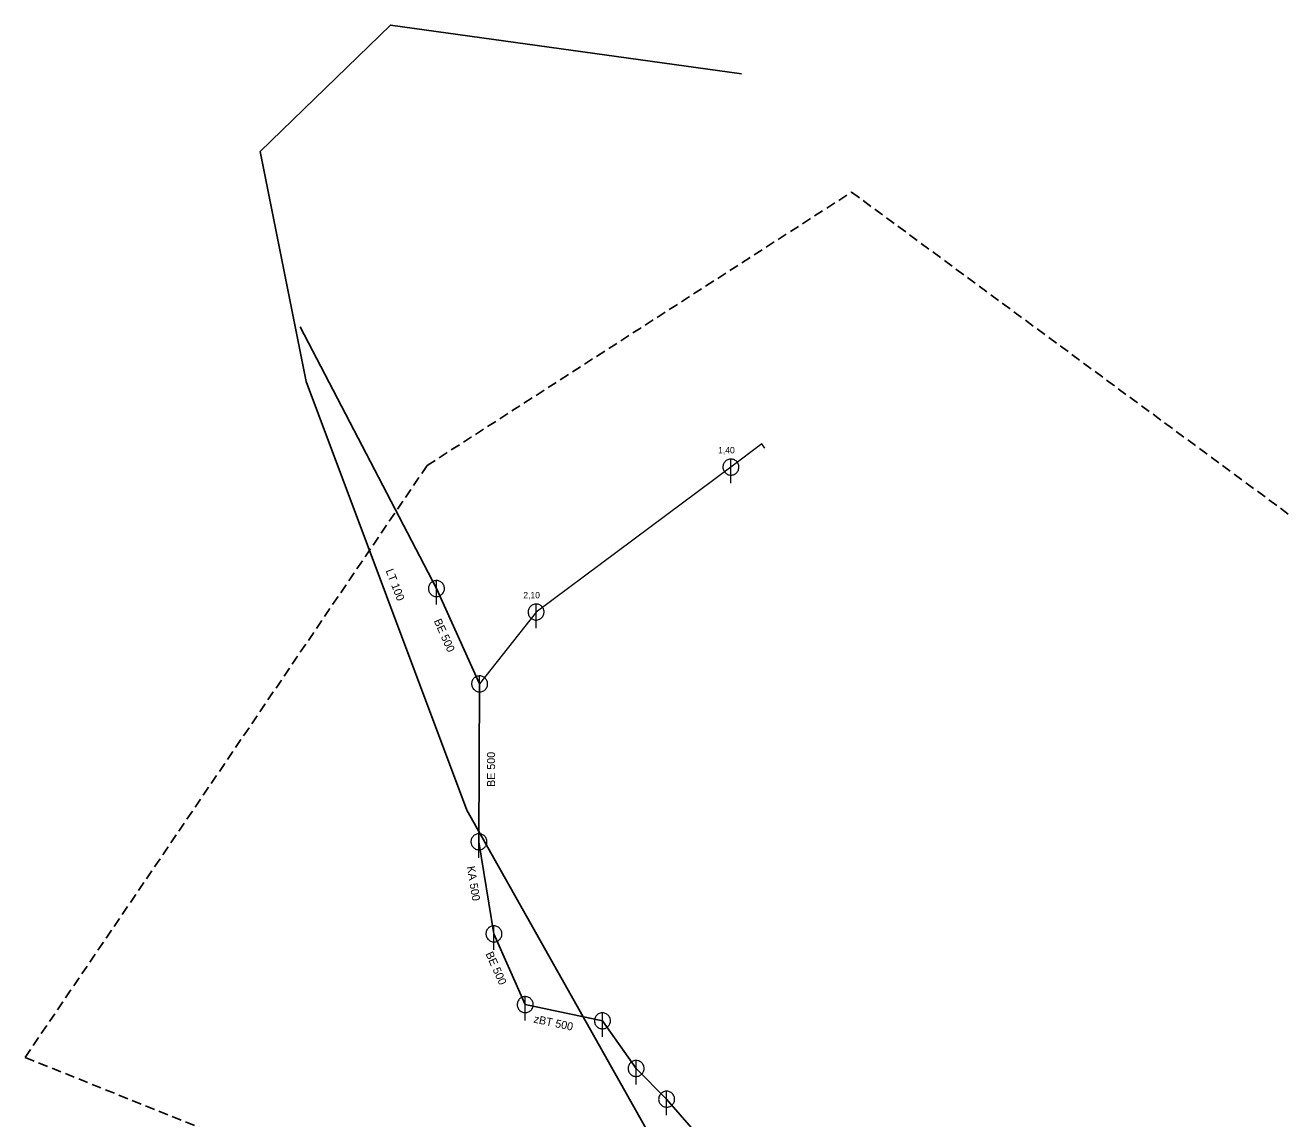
# Model space of a CAD drawing. Extents: x -687195 to -686201, y -974149 to -973877.
# Drawn here: x -687195.2 to -687038.1, y -974013.8 to -973877.2 of the extents above; entities that cross this region are included whole.
import ezdxf

# ---------------------------------------------------------------- set-up
doc = ezdxf.new("R2010")
doc.units = 0
doc.header["$LTSCALE"] = 0.4
doc.linetypes.add('MEDIUM_DASHED', pattern=[4.5, 3, -1.5])
doc.layers.add('1', color=7, linetype='Continuous')
for name, color, linetype, lineweight in [('11', 7, 'Continuous', 13), ('14', 7, 'Continuous', 25), ('17', 7, 'Continuous', 25), ('22', 7, 'Continuous', 13), ('63', 7, 'MEDIUM_DASHED', 25)]:
    doc.layers.add(name, color=color, linetype=linetype, lineweight=lineweight)

msp = doc.modelspace()

# ---------------------------------------------------------------- linework, layer by layer
at = {"layer": '11'}
for p, q in [((-687106.99, -973932.4), (-687131.34, -973950.51)), ((-687131.34, -973950.51), (-687138.399, -973959.489))]:
    msp.add_line(p, q, dxfattribs=at)
msp.add_lwpolyline([(-687102.74, -973930.05), (-687103.13, -973929.48), (-687106.99, -973932.4)], dxfattribs=at)
at = {"layer": '14'}
for p, q in [((-687160.836, -973914.878), (-687143.793, -973947.573)), ((-687143.793, -973947.573), (-687138.399, -973959.489)), ((-687138.399, -973959.489), (-687138.481, -973979.218)), ((-687138.481, -973979.218), (-687136.605, -973990.725)), ((-687136.605, -973990.725), (-687132.697, -973999.562)), ((-687132.697, -973999.562), (-687123.045, -974001.587)), ((-687123.045, -974001.587), (-687118.837, -974007.541)), ((-687118.837, -974007.541), (-687115.021, -974011.379)), ((-687115.021, -974011.379), (-687111.634, -974015.295))]:
    msp.add_line(p, q, dxfattribs=at)
at = {"layer": '17'}
msp.add_lwpolyline([(-687124.395, -974028.598), (-687113.714, -974021.973), (-687139.989, -973975.271), (-687160.068, -973921.704), (-687165.829, -973892.978), (-687149.548, -973877.175), (-687105.661, -973883.258)], dxfattribs=at)
at = {"layer": '22'}
for p, q in [((-687106.99, -973934.4), (-687106.989, -973931.4)), ((-687143.793, -973949.573), (-687143.792, -973946.573)), ((-687131.34, -973952.51), (-687131.339, -973949.51)), ((-687138.399, -973961.489), (-687138.398, -973958.489)), ((-687138.481, -973981.218), (-687138.48, -973978.218)), ((-687136.605, -973992.725), (-687136.604, -973989.725)), ((-687132.697, -974001.562), (-687132.696, -973998.562)), ((-687123.045, -974003.587), (-687123.044, -974000.587)), ((-687118.837, -974009.541), (-687118.836, -974006.541)), ((-687115.021, -974013.379), (-687115.02, -974010.379))]:
    msp.add_line(p, q, dxfattribs=at)
for points in [[(-687105.99, -973932.4), (-687105.995, -973932.291), (-687106.013, -973932.183), (-687106.043, -973932.077), (-687106.083, -973931.976), (-687106.135, -973931.879), (-687106.197, -973931.789), (-687106.269, -973931.706), (-687106.349, -973931.632), (-687106.437, -973931.566), (-687106.531, -973931.511), (-687106.631, -973931.466), (-687106.736, -973931.433), (-687106.843, -973931.411), (-687106.952, -973931.401), (-687107.062, -973931.403), (-687107.17, -973931.417), (-687107.277, -973931.442), (-687107.38, -973931.479), (-687107.478, -973931.528), (-687107.57, -973931.586), (-687107.656, -973931.655), (-687107.733, -973931.732), (-687107.802, -973931.818), (-687107.861, -973931.91), (-687107.909, -973932.008), (-687107.946, -973932.111), (-687107.972, -973932.218), (-687107.986, -973932.326), (-687107.989, -973932.436), (-687107.979, -973932.545), (-687107.958, -973932.652), (-687107.924, -973932.756), (-687107.88, -973932.856), (-687107.825, -973932.951), (-687107.759, -973933.039), (-687107.685, -973933.119), (-687107.602, -973933.191), (-687107.512, -973933.253), (-687107.416, -973933.305), (-687107.314, -973933.346), (-687107.209, -973933.376), (-687107.101, -973933.394), (-687106.991, -973933.4), (-687106.882, -973933.394), (-687106.774, -973933.376), (-687106.669, -973933.347), (-687106.567, -973933.306), (-687106.47, -973933.254), (-687106.38, -973933.192), (-687106.297, -973933.121), (-687106.222, -973933.041), (-687106.157, -973932.953), (-687106.101, -973932.859), (-687106.057, -973932.759), (-687106.023, -973932.655), (-687106.001, -973932.547), (-687105.991, -973932.438)], [(-687142.793, -973947.573), (-687142.798, -973947.464), (-687142.816, -973947.356), (-687142.846, -973947.25), (-687142.886, -973947.149), (-687142.938, -973947.052), (-687143, -973946.962), (-687143.072, -973946.879), (-687143.152, -973946.805), (-687143.24, -973946.739), (-687143.334, -973946.684), (-687143.434, -973946.639), (-687143.539, -973946.606), (-687143.646, -973946.584), (-687143.755, -973946.574), (-687143.865, -973946.576), (-687143.973, -973946.59), (-687144.08, -973946.615), (-687144.183, -973946.652), (-687144.281, -973946.701), (-687144.373, -973946.759), (-687144.459, -973946.828), (-687144.536, -973946.905), (-687144.605, -973946.991), (-687144.664, -973947.083), (-687144.712, -973947.181), (-687144.749, -973947.284), (-687144.775, -973947.391), (-687144.789, -973947.499), (-687144.792, -973947.609), (-687144.782, -973947.718), (-687144.761, -973947.825), (-687144.727, -973947.929), (-687144.683, -973948.029), (-687144.628, -973948.124), (-687144.562, -973948.212), (-687144.488, -973948.292), (-687144.405, -973948.364), (-687144.315, -973948.426), (-687144.219, -973948.478), (-687144.117, -973948.519), (-687144.012, -973948.549), (-687143.904, -973948.567), (-687143.794, -973948.573), (-687143.685, -973948.567), (-687143.577, -973948.549), (-687143.472, -973948.52), (-687143.37, -973948.479), (-687143.273, -973948.427), (-687143.183, -973948.365), (-687143.1, -973948.294), (-687143.025, -973948.214), (-687142.96, -973948.126), (-687142.904, -973948.032), (-687142.86, -973947.932), (-687142.826, -973947.828), (-687142.804, -973947.72), (-687142.794, -973947.611)], [(-687130.34, -973950.51), (-687130.345, -973950.401), (-687130.363, -973950.293), (-687130.393, -973950.187), (-687130.433, -973950.086), (-687130.485, -973949.989), (-687130.547, -973949.899), (-687130.619, -973949.816), (-687130.699, -973949.742), (-687130.787, -973949.676), (-687130.881, -973949.621), (-687130.981, -973949.576), (-687131.086, -973949.543), (-687131.193, -973949.521), (-687131.302, -973949.511), (-687131.412, -973949.513), (-687131.52, -973949.527), (-687131.627, -973949.552), (-687131.73, -973949.589), (-687131.828, -973949.638), (-687131.92, -973949.696), (-687132.006, -973949.765), (-687132.083, -973949.842), (-687132.152, -973949.928), (-687132.211, -973950.02), (-687132.259, -973950.118), (-687132.296, -973950.221), (-687132.322, -973950.328), (-687132.336, -973950.436), (-687132.339, -973950.546), (-687132.329, -973950.655), (-687132.308, -973950.762), (-687132.274, -973950.866), (-687132.23, -973950.966), (-687132.175, -973951.061), (-687132.109, -973951.149), (-687132.035, -973951.229), (-687131.952, -973951.301), (-687131.862, -973951.363), (-687131.766, -973951.415), (-687131.664, -973951.456), (-687131.559, -973951.486), (-687131.451, -973951.504), (-687131.341, -973951.51), (-687131.232, -973951.504), (-687131.124, -973951.486), (-687131.019, -973951.457), (-687130.917, -973951.416), (-687130.82, -973951.364), (-687130.73, -973951.302), (-687130.647, -973951.231), (-687130.572, -973951.151), (-687130.507, -973951.063), (-687130.451, -973950.969), (-687130.407, -973950.869), (-687130.373, -973950.765), (-687130.351, -973950.657), (-687130.341, -973950.548)], [(-687137.399, -973959.489), (-687137.404, -973959.38), (-687137.422, -973959.272), (-687137.452, -973959.166), (-687137.492, -973959.065), (-687137.544, -973958.968), (-687137.606, -973958.878), (-687137.678, -973958.795), (-687137.758, -973958.721), (-687137.846, -973958.655), (-687137.94, -973958.6), (-687138.04, -973958.555), (-687138.145, -973958.522), (-687138.252, -973958.5), (-687138.361, -973958.49), (-687138.471, -973958.492), (-687138.579, -973958.506), (-687138.686, -973958.531), (-687138.789, -973958.568), (-687138.887, -973958.617), (-687138.979, -973958.675), (-687139.065, -973958.744), (-687139.142, -973958.821), (-687139.211, -973958.907), (-687139.27, -973958.999), (-687139.318, -973959.097), (-687139.355, -973959.2), (-687139.381, -973959.307), (-687139.395, -973959.415), (-687139.398, -973959.525), (-687139.388, -973959.634), (-687139.367, -973959.741), (-687139.333, -973959.845), (-687139.289, -973959.945), (-687139.234, -973960.04), (-687139.168, -973960.128), (-687139.094, -973960.208), (-687139.011, -973960.28), (-687138.921, -973960.342), (-687138.825, -973960.394), (-687138.723, -973960.435), (-687138.618, -973960.465), (-687138.51, -973960.483), (-687138.4, -973960.489), (-687138.291, -973960.483), (-687138.183, -973960.465), (-687138.078, -973960.436), (-687137.976, -973960.395), (-687137.879, -973960.343), (-687137.789, -973960.281), (-687137.706, -973960.21), (-687137.631, -973960.13), (-687137.566, -973960.042), (-687137.51, -973959.948), (-687137.466, -973959.848), (-687137.432, -973959.744), (-687137.41, -973959.636), (-687137.4, -973959.527)], [(-687137.481, -973979.218), (-687137.486, -973979.109), (-687137.504, -973979.001), (-687137.534, -973978.895), (-687137.574, -973978.794), (-687137.626, -973978.697), (-687137.688, -973978.607), (-687137.76, -973978.524), (-687137.84, -973978.45), (-687137.928, -973978.384), (-687138.022, -973978.329), (-687138.122, -973978.284), (-687138.227, -973978.251), (-687138.334, -973978.229), (-687138.443, -973978.219), (-687138.553, -973978.221), (-687138.661, -973978.235), (-687138.768, -973978.26), (-687138.871, -973978.297), (-687138.969, -973978.346), (-687139.061, -973978.404), (-687139.147, -973978.473), (-687139.224, -973978.55), (-687139.293, -973978.636), (-687139.352, -973978.728), (-687139.4, -973978.826), (-687139.437, -973978.929), (-687139.463, -973979.036), (-687139.477, -973979.144), (-687139.48, -973979.254), (-687139.47, -973979.363), (-687139.449, -973979.47), (-687139.415, -973979.574), (-687139.371, -973979.674), (-687139.316, -973979.769), (-687139.25, -973979.857), (-687139.176, -973979.937), (-687139.093, -973980.009), (-687139.003, -973980.071), (-687138.907, -973980.123), (-687138.805, -973980.164), (-687138.7, -973980.194), (-687138.592, -973980.212), (-687138.482, -973980.218), (-687138.373, -973980.212), (-687138.265, -973980.194), (-687138.16, -973980.165), (-687138.058, -973980.124), (-687137.961, -973980.072), (-687137.871, -973980.01), (-687137.788, -973979.939), (-687137.713, -973979.859), (-687137.648, -973979.771), (-687137.592, -973979.677), (-687137.548, -973979.577), (-687137.514, -973979.473), (-687137.492, -973979.365), (-687137.482, -973979.256)], [(-687135.605, -973990.725), (-687135.61, -973990.616), (-687135.628, -973990.508), (-687135.658, -973990.402), (-687135.698, -973990.301), (-687135.75, -973990.204), (-687135.812, -973990.114), (-687135.884, -973990.031), (-687135.964, -973989.957), (-687136.052, -973989.891), (-687136.146, -973989.836), (-687136.246, -973989.791), (-687136.351, -973989.758), (-687136.458, -973989.736), (-687136.567, -973989.726), (-687136.677, -973989.728), (-687136.785, -973989.742), (-687136.892, -973989.767), (-687136.995, -973989.804), (-687137.093, -973989.853), (-687137.185, -973989.911), (-687137.271, -973989.98), (-687137.348, -973990.057), (-687137.417, -973990.143), (-687137.476, -973990.235), (-687137.524, -973990.333), (-687137.561, -973990.436), (-687137.587, -973990.543), (-687137.601, -973990.651), (-687137.604, -973990.761), (-687137.594, -973990.87), (-687137.573, -973990.977), (-687137.539, -973991.081), (-687137.495, -973991.181), (-687137.44, -973991.276), (-687137.374, -973991.364), (-687137.3, -973991.444), (-687137.217, -973991.516), (-687137.127, -973991.578), (-687137.031, -973991.63), (-687136.929, -973991.671), (-687136.824, -973991.701), (-687136.716, -973991.719), (-687136.606, -973991.725), (-687136.497, -973991.719), (-687136.389, -973991.701), (-687136.284, -973991.672), (-687136.182, -973991.631), (-687136.085, -973991.579), (-687135.995, -973991.517), (-687135.912, -973991.446), (-687135.837, -973991.366), (-687135.772, -973991.278), (-687135.716, -973991.184), (-687135.672, -973991.084), (-687135.638, -973990.98), (-687135.616, -973990.872), (-687135.606, -973990.763)], [(-687131.697, -973999.562), (-687131.702, -973999.453), (-687131.72, -973999.345), (-687131.75, -973999.239), (-687131.79, -973999.138), (-687131.842, -973999.041), (-687131.904, -973998.951), (-687131.976, -973998.868), (-687132.056, -973998.794), (-687132.144, -973998.728), (-687132.238, -973998.673), (-687132.338, -973998.628), (-687132.443, -973998.595), (-687132.55, -973998.573), (-687132.659, -973998.563), (-687132.769, -973998.565), (-687132.877, -973998.579), (-687132.984, -973998.604), (-687133.087, -973998.641), (-687133.185, -973998.69), (-687133.277, -973998.748), (-687133.363, -973998.817), (-687133.44, -973998.894), (-687133.509, -973998.98), (-687133.568, -973999.072), (-687133.616, -973999.17), (-687133.653, -973999.273), (-687133.679, -973999.38), (-687133.693, -973999.488), (-687133.696, -973999.598), (-687133.686, -973999.707), (-687133.665, -973999.814), (-687133.631, -973999.918), (-687133.587, -974000.018), (-687133.532, -974000.113), (-687133.466, -974000.201), (-687133.392, -974000.281), (-687133.309, -974000.353), (-687133.219, -974000.415), (-687133.123, -974000.467), (-687133.021, -974000.508), (-687132.916, -974000.538), (-687132.808, -974000.556), (-687132.698, -974000.562), (-687132.589, -974000.556), (-687132.481, -974000.538), (-687132.376, -974000.509), (-687132.274, -974000.468), (-687132.177, -974000.416), (-687132.087, -974000.354), (-687132.004, -974000.283), (-687131.929, -974000.203), (-687131.864, -974000.115), (-687131.808, -974000.021), (-687131.764, -973999.921), (-687131.73, -973999.817), (-687131.708, -973999.709), (-687131.698, -973999.6)], [(-687122.045, -974001.587), (-687122.05, -974001.478), (-687122.068, -974001.37), (-687122.098, -974001.264), (-687122.138, -974001.163), (-687122.19, -974001.066), (-687122.252, -974000.976), (-687122.324, -974000.893), (-687122.404, -974000.819), (-687122.492, -974000.753), (-687122.586, -974000.698), (-687122.686, -974000.653), (-687122.791, -974000.62), (-687122.898, -974000.598), (-687123.007, -974000.588), (-687123.117, -974000.59), (-687123.225, -974000.604), (-687123.332, -974000.629), (-687123.435, -974000.666), (-687123.533, -974000.715), (-687123.625, -974000.773), (-687123.711, -974000.842), (-687123.788, -974000.919), (-687123.857, -974001.005), (-687123.916, -974001.097), (-687123.964, -974001.195), (-687124.001, -974001.298), (-687124.027, -974001.405), (-687124.041, -974001.513), (-687124.044, -974001.623), (-687124.034, -974001.732), (-687124.013, -974001.839), (-687123.979, -974001.943), (-687123.935, -974002.043), (-687123.88, -974002.138), (-687123.814, -974002.226), (-687123.74, -974002.306), (-687123.657, -974002.378), (-687123.567, -974002.44), (-687123.471, -974002.492), (-687123.369, -974002.533), (-687123.264, -974002.563), (-687123.156, -974002.581), (-687123.046, -974002.587), (-687122.937, -974002.581), (-687122.829, -974002.563), (-687122.724, -974002.534), (-687122.622, -974002.493), (-687122.525, -974002.441), (-687122.435, -974002.379), (-687122.352, -974002.308), (-687122.277, -974002.228), (-687122.212, -974002.14), (-687122.156, -974002.046), (-687122.112, -974001.946), (-687122.078, -974001.842), (-687122.056, -974001.734), (-687122.046, -974001.625)], [(-687117.837, -974007.541), (-687117.842, -974007.432), (-687117.86, -974007.324), (-687117.89, -974007.218), (-687117.93, -974007.117), (-687117.982, -974007.02), (-687118.044, -974006.93), (-687118.116, -974006.847), (-687118.196, -974006.773), (-687118.284, -974006.707), (-687118.378, -974006.652), (-687118.478, -974006.607), (-687118.583, -974006.574), (-687118.69, -974006.552), (-687118.799, -974006.542), (-687118.909, -974006.544), (-687119.017, -974006.558), (-687119.124, -974006.583), (-687119.227, -974006.62), (-687119.325, -974006.669), (-687119.417, -974006.727), (-687119.503, -974006.796), (-687119.58, -974006.873), (-687119.649, -974006.959), (-687119.708, -974007.051), (-687119.756, -974007.149), (-687119.793, -974007.252), (-687119.819, -974007.359), (-687119.833, -974007.467), (-687119.836, -974007.577), (-687119.826, -974007.686), (-687119.805, -974007.793), (-687119.771, -974007.897), (-687119.727, -974007.997), (-687119.672, -974008.092), (-687119.606, -974008.18), (-687119.532, -974008.26), (-687119.449, -974008.332), (-687119.359, -974008.394), (-687119.263, -974008.446), (-687119.161, -974008.487), (-687119.056, -974008.517), (-687118.948, -974008.535), (-687118.838, -974008.541), (-687118.729, -974008.535), (-687118.621, -974008.517), (-687118.516, -974008.488), (-687118.414, -974008.447), (-687118.317, -974008.395), (-687118.227, -974008.333), (-687118.144, -974008.262), (-687118.069, -974008.182), (-687118.004, -974008.094), (-687117.948, -974008), (-687117.904, -974007.9), (-687117.87, -974007.796), (-687117.848, -974007.688), (-687117.838, -974007.579)], [(-687114.021, -974011.379), (-687114.026, -974011.27), (-687114.044, -974011.162), (-687114.074, -974011.056), (-687114.114, -974010.955), (-687114.166, -974010.858), (-687114.228, -974010.768), (-687114.3, -974010.685), (-687114.38, -974010.611), (-687114.468, -974010.545), (-687114.562, -974010.49), (-687114.662, -974010.445), (-687114.767, -974010.412), (-687114.874, -974010.39), (-687114.983, -974010.38), (-687115.093, -974010.382), (-687115.201, -974010.396), (-687115.308, -974010.421), (-687115.411, -974010.458), (-687115.509, -974010.507), (-687115.601, -974010.565), (-687115.687, -974010.634), (-687115.764, -974010.711), (-687115.833, -974010.797), (-687115.892, -974010.889), (-687115.94, -974010.987), (-687115.977, -974011.09), (-687116.003, -974011.197), (-687116.017, -974011.305), (-687116.02, -974011.415), (-687116.01, -974011.524), (-687115.989, -974011.631), (-687115.955, -974011.735), (-687115.911, -974011.835), (-687115.856, -974011.93), (-687115.79, -974012.018), (-687115.716, -974012.098), (-687115.633, -974012.17), (-687115.543, -974012.232), (-687115.447, -974012.284), (-687115.345, -974012.325), (-687115.24, -974012.355), (-687115.132, -974012.373), (-687115.022, -974012.379), (-687114.913, -974012.373), (-687114.805, -974012.355), (-687114.7, -974012.326), (-687114.598, -974012.285), (-687114.501, -974012.233), (-687114.411, -974012.171), (-687114.328, -974012.1), (-687114.253, -974012.02), (-687114.188, -974011.932), (-687114.132, -974011.838), (-687114.088, -974011.738), (-687114.054, -974011.634), (-687114.032, -974011.526), (-687114.022, -974011.417)]]:
    msp.add_lwpolyline(points, close=True, dxfattribs=at)
at = {"layer": '63'}
msp.add_lwpolyline([(-687195.201, -974006.159), (-687144.96, -973932.203), (-687144.96, -973932.203), (-687091.904, -973898.039), (-687091.904, -973898.039), (-686884.104, -974051.176), (-686884.104, -974051.176), (-686970.922, -974135.181), (-686970.922, -974135.181), (-687042.868, -974074.89), (-687042.868, -974074.89), (-687130.088, -974149.248), (-687130.088, -974149.248), (-687180.33, -974098.203), (-687180.33, -974098.203), (-687127.274, -974033.491), (-687127.274, -974033.491)], close=True, dxfattribs=at)

# ---------------------------------------------------------------- texts
at = {"layer": '1'}
for s, p in [('1,40', (-687108.59, -973930.688)), ('2,10', (-687132.939, -973948.798))]:
    msp.add_text(s, height=0.8, dxfattribs=at).set_placement(p)
for s, rotation, p in [('LT 100', 291, (-687150.159, -973945.332)), ('BE 500', 294, (-687144.141, -973951.617)), ('BE 500', 90, (-687136.467, -973972.362)), ('KA 500', 279, (-687139.985, -973982.329)), ('BE 500', 294, (-687137.679, -973993.202)), ('zBT 500 ', 348, (-687131.704, -974001.798))]:
    msp.add_text(s, height=1, rotation=rotation, dxfattribs=at).set_placement(p)

doc.saveas('drawing.dxf')
